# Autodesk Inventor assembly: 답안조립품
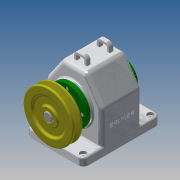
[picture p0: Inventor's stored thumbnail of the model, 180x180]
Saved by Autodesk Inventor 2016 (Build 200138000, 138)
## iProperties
Created: 2016-12
Part Number: 답안조립품
Document SubType Name: Assembly
Designer: Administrator
Author: Administrator
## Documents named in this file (15)
- D:\461207V1003\답안조립품.iam
- D:\461207V1003\본체.ipt
- D:\461207V1003\V-벨트풀리.ipt
- D:\461207V1003\뒤커버.ipt
- D:\461207V1003\멈춤나사 - M4x10.ipt
- D:\461207V1003\베어링 6203.ipt
- D:\461207V1003\볼트 M3 x 8.ipt
- D:\461207V1003\볼트 M3 x 10.ipt
- D:\461207V1003\부시.ipt
- D:\461207V1003\스퍼기어.ipt
- D:\461207V1003\앞커버.ipt
- D:\461207V1003\오일씰 28 40 8.ipt
- D:\461207V1003\축.ipt
- D:\461207V1003\키 - 5 x 5 x 18.ipt
- D:\461207V1003\키 - 6 x 6 x 22.ipt
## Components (9 placed, 3 different names)
1. V-벨트풀리:1 — 각도:2
2. ISO 4762 M3 x 10:1
3. ISO 4762 M3 x 10:2
4. ISO 4762 M3 x 10:3
5. ISO 4762 M3 x 10:4
6. ISO 4762 M3 x 8:1
7. ISO 4762 M3 x 8:2
8. ISO 4762 M3 x 8:3
9. ISO 4762 M3 x 8:4
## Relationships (1: Angle 1)
- 각도:2 [Angle]: V-벨트풀리:1
